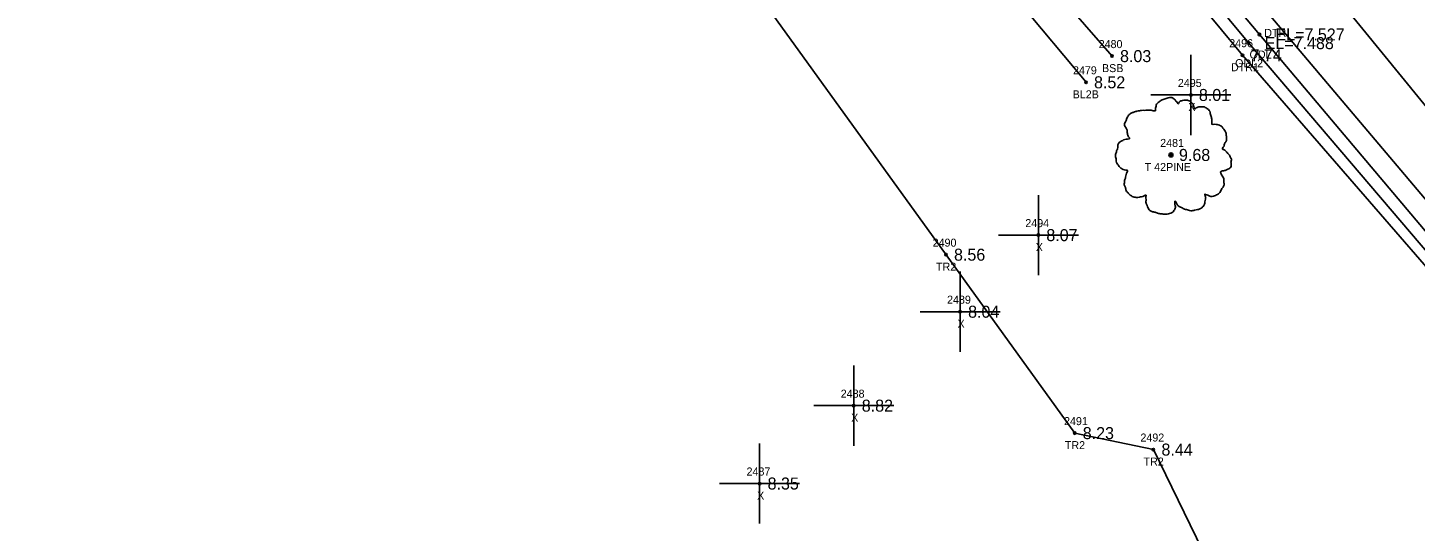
# Model space of a CAD drawing. Extents: x 2042211 to 2045853, y 303080 to 309569.
# Drawn here: x 2044468.4 to 2044641.9, y 304414.4 to 304477.2 of the extents above; entities that cross this region are included whole.
import ezdxf

# ---------------------------------------------------------------- set-up
doc = ezdxf.new("R2010")
doc.units = 0
for name, color, linetype in [('BR_500YR_SCOUR', 7, 'Continuous'), ('RD_DTM_BkLn1', 7, 'Continuous'), ('RD_DTM_BkLn2', 7, 'Continuous'), ('RD_DTM_BkLn_txCode', 7, 'Continuous'), ('RD_EX_H2O', 7, 'Continuous'), ('RD_EX_H2O_txCode', 7, 'Continuous'), ('RD_EX_Misc', 7, 'Continuous'), ('RD_EX_Misc_txCode', 7, 'Continuous'), ('RD_EX_TX_H2O_ELEV', 7, 'Continuous'), ('RD_EX_TX_Misc_ELEV', 7, 'Continuous'), ('RD_EX_TX_VEG_ELEV', 7, 'Continuous'), ('RD_EX_VEG_txCode', 7, 'Continuous'), ('RD_SMD_Locator', 7, 'Continuous')]:
    doc.layers.add(name, color=color, linetype=linetype)

msp = doc.modelspace()

# ---------------------------------------------------------------- linework, layer by layer
at = {"layer": 'BR_500YR_SCOUR'}
msp.add_lwpolyline([(2044509.17, 304539.98), (2044524.22, 304524.97), (2044542.12, 304505.8), (2044583.21, 304448.88), (2044599.3, 304426.6), (2044609.14, 304424.55), (2044616.83, 304408.81), (2044657.84, 304363.53)], dxfattribs=at)
for centre, radius in [((2044611.33, 304461.33), 0.25), ((2044611.33, 304461.33), 0.15), ((2044611.32, 304461.31), 0.0001), ((2044583.21, 304448.88), 0.15), ((2044599.3, 304426.6), 0.15), ((2044609.14, 304424.55), 0.15)]:
    msp.add_circle(centre, radius, dxfattribs=at)
for points in [[(2044611.46, 304468.5), (2044611.16, 304468.52), (2044610.84, 304468.42), (2044610.59, 304468.32), (2044610.36, 304468.25), (2044610.14, 304468.15), (2044609.84, 304467.97), (2044609.61, 304467.77), (2044609.49, 304467.53), (2044609.44, 304467.3), (2044609.39, 304467.03), (2044609.39, 304466.85), (2044609.26, 304466.83), (2044609.11, 304466.85), (2044608.86, 304466.93), (2044608.61, 304466.93), (2044608.36, 304466.93), (2044608.01, 304466.9), (2044607.66, 304466.9), (2044607.39, 304466.85), (2044607.06, 304466.8), (2044606.69, 304466.68), (2044606.34, 304466.55), (2044606.04, 304466.3), (2044605.79, 304465.83), (2044605.66, 304465.48), (2044605.51, 304465.23), (2044605.66, 304464.78), (2044605.84, 304464.43), (2044605.86, 304464.23), (2044605.94, 304463.8), (2044606.04, 304463.58), (2044606.16, 304463.38), (2044606.09, 304463.35), (2044605.71, 304463.3), (2044605.41, 304463.2), (2044604.99, 304462.98), (2044604.77, 304462.75), (2044604.67, 304462.43), (2044604.64, 304462.08), (2044604.54, 304461.88), (2044604.47, 304461.6), (2044604.44, 304461.53), (2044604.39, 304461.2), (2044604.49, 304460.75), (2044604.52, 304460.4), (2044604.64, 304460.18), (2044604.79, 304460), (2044604.96, 304459.75), (2044605.36, 304459.53), (2044605.69, 304459.43), (2044605.89, 304459.4), (2044605.71, 304458.9), (2044605.66, 304458.55), (2044605.54, 304458.15), (2044605.54, 304458.08), (2044605.49, 304457.6), (2044605.64, 304457.28), (2044605.71, 304456.9), (2044605.89, 304456.68), (2044606.16, 304456.38), (2044606.49, 304456.16), (2044606.99, 304456.03), (2044607.39, 304456.06), (2044607.96, 304456.23), (2044608.21, 304456.3), (2044608.19, 304456.13), (2044608.21, 304455.76), (2044608.21, 304455.33), (2044608.36, 304455.01), (2044608.46, 304454.73), (2044608.61, 304454.48), (2044608.94, 304454.26), (2044609.34, 304454.18), (2044609.76, 304454.03), (2044610.21, 304453.96), (2044610.71, 304453.93), (2044611.31, 304454.08), (2044611.59, 304454.21), (2044611.69, 304454.38), (2044611.89, 304454.76), (2044611.84, 304454.98), (2044611.86, 304455.58), (2044611.96, 304455.41), (2044612.14, 304455.06), (2044612.64, 304454.76), (2044613.04, 304454.58), (2044613.51, 304454.43), (2044613.81, 304454.36), (2044614.29, 304454.43), (2044614.66, 304454.51), (2044615.04, 304454.63), (2044615.34, 304454.91), (2044615.51, 304455.18), (2044615.56, 304455.46), (2044615.64, 304455.83), (2044615.69, 304456.01)], [(2044615.69, 304456.01), (2044615.61, 304456.18), (2044615.56, 304456.43), (2044615.64, 304456.4), (2044615.81, 304456.35), (2044616.09, 304456.23), (2044616.31, 304456.16), (2044616.63, 304456.18), (2044616.91, 304456.28), (2044617.36, 304456.55), (2044617.63, 304457.03), (2044617.91, 304457.43), (2044617.98, 304457.75), (2044617.93, 304457.98), (2044617.91, 304458.48), (2044617.71, 304458.73), (2044617.66, 304458.85), (2044617.56, 304459.25), (2044617.63, 304459.3), (2044617.91, 304459.35), (2044618.28, 304459.48), (2044618.56, 304459.6), (2044618.78, 304459.78), (2044618.86, 304460), (2044618.83, 304460.4), (2044618.88, 304460.8), (2044618.81, 304460.95), (2044618.71, 304461.1), (2044618.63, 304461.3), (2044618.48, 304461.45), (2044618.38, 304461.6), (2044618.28, 304461.7), (2044618.16, 304461.85), (2044617.98, 304461.98), (2044617.83, 304462.03), (2044617.78, 304462.18), (2044617.93, 304462.38), (2044617.98, 304462.48), (2044618.01, 304462.7), (2044618.23, 304463.05), (2044618.28, 304463.45), (2044618.23, 304463.88), (2044618.18, 304464.15), (2044618.03, 304464.43), (2044617.83, 304464.68), (2044617.71, 304464.85), (2044617.53, 304464.98), (2044617.21, 304465.1), (2044616.96, 304465.15), (2044616.61, 304465.15), (2044616.41, 304465.2), (2044616.43, 304465.25), (2044616.43, 304465.4), (2044616.43, 304465.68), (2044616.36, 304466.13), (2044616.21, 304466.63), (2044616.21, 304466.65), (2044616.11, 304466.9), (2044615.89, 304467.1), (2044615.71, 304467.2), (2044615.51, 304467.33), (2044615.26, 304467.35), (2044614.96, 304467.35), (2044614.69, 304467.3), (2044614.49, 304467.2), (2044614.31, 304467.08), (2044614.24, 304467.23), (2044614.14, 304467.53), (2044614.09, 304467.67), (2044613.94, 304467.85), (2044613.71, 304468.05), (2044613.26, 304468.17), (2044612.64, 304468.1), (2044612.34, 304467.9), (2044612.19, 304467.72), (2044612.14, 304467.85), (2044611.94, 304468.05), (2044611.84, 304468.22), (2044611.66, 304468.35), (2044611.51, 304468.45), (2044611.41, 304468.5)]]:
    msp.add_spline(points, degree=3, dxfattribs=at)
at = {"layer": 'RD_DTM_BkLn1'}
for points in [[(2043798.36, 305479.17), (2043862.32, 305402.71), (2043926.37, 305326.69), (2043989.74, 305249.79), (2043988.33, 305246.75), (2043991.19, 305243.51), (2043994.75, 305243.65), (2044053.09, 305173.37), (2044116.28, 305094.9), (2044180.2, 305019.52), (2044245.63, 304943.51), (2044308.37, 304866.05), (2044373.1, 304789.96), (2044438.35, 304712.62), (2044501.57, 304636.05), (2044528.47, 304600.32), (2044565.87, 304558.85), (2044630.47, 304482.97), (2044694.06, 304405.2), (2044697.06, 304397.81), (2044701.81, 304392.08), (2044707.96, 304388.87), (2044759.04, 304329.78)], [(2044527.03, 304557.93), (2044544.9, 304537.03), (2044600.71, 304470.4)]]:
    msp.add_lwpolyline(points, dxfattribs=at)
at = {"layer": 'RD_DTM_BkLn2'}
msp.add_lwpolyline([(2044528.83, 304561.67), (2044546.66, 304539.23), (2044603.96, 304473.67)], dxfattribs=at)
at = {"layer": 'RD_EX_H2O'}
for points in [[(2044526.69, 304588.12), (2044529.75, 304589.5), (2044560.23, 304553.15), (2044624.26, 304478.07), (2044679.39, 304412.98), (2044689.21, 304400.4), (2044696.61, 304396.14)], [(2044526.69, 304588.12), (2044524.46, 304585.8), (2044557.52, 304549.44), (2044620.27, 304473.78), (2044676.08, 304409.54), (2044675.89, 304404.78), (2044683.56, 304394.92), (2044688.93, 304389.15), (2044690.58, 304383.03), (2044681.72, 304360.31), (2044669.72, 304323.23)], [(2044528.02, 304587.51), (2044559.1, 304551.6), (2044622.39, 304476.37), (2044677.57, 304411.07), (2044687.25, 304399.14), (2044692.5, 304393.31)], [(2044526.69, 304586.11), (2044558.35, 304550.68), (2044621.04, 304475.29), (2044676.74, 304410.12), (2044678.19, 304404.53), (2044685.26, 304396.55), (2044691.41, 304390.93)]]:
    msp.add_lwpolyline(points, dxfattribs=at)
at = {"layer": 'RD_EX_Misc'}
for p, q in [((2044613.82, 304463.82), (2044613.82, 304473.82)), ((2044608.82, 304468.82), (2044618.82, 304468.82)), ((2044594.75, 304446.32), (2044594.75, 304456.32)), ((2044589.75, 304451.32), (2044599.75, 304451.32)), ((2044584.97, 304436.76), (2044584.97, 304446.76)), ((2044579.97, 304441.76), (2044589.97, 304441.76)), ((2044571.68, 304425.03), (2044571.68, 304435.03)), ((2044566.68, 304430.03), (2044576.68, 304430.03)), ((2044559.91, 304415.31), (2044559.91, 304425.31)), ((2044554.91, 304420.31), (2044564.91, 304420.31))]:
    msp.add_line(p, q, dxfattribs=at)
at = {"layer": 'RD_SMD_Locator'}
for centre in [(2044622.39, 304476.37), (2044621.04, 304475.29), (2044603.96, 304473.67), (2044620.27, 304473.78), (2044600.71, 304470.4), (2044613.82, 304468.82), (2044594.75, 304451.32), (2044584.97, 304441.76), (2044571.68, 304430.03), (2044559.91, 304420.31)]:
    msp.add_circle(centre, 0.15, dxfattribs=at)

# ---------------------------------------------------------------- texts
at = {"layer": 'RD_DTM_BkLn_txCode'}
for s, p in [('2480', (2044602.29, 304474.67)), ('BSB', (2044602.71, 304471.67)), ('2479', (2044599.08, 304471.4)), ('BL2B', (2044599.04, 304468.4))]:
    msp.add_text(s, height=1, dxfattribs=at).set_placement(p)
at = {"layer": 'RD_EX_H2O_txCode'}
for s, p in [('DTR', (2044622.99, 304476.07)), ('2496', (2044618.61, 304474.78)), ('ODL', (2044621.15, 304473.37)), ('DTR1', (2044618.83, 304471.78)), ('ODL2', (2044619.35, 304472.29))]:
    msp.add_text(s, height=1, dxfattribs=at).set_placement(p)
at = {"layer": 'RD_EX_Misc_txCode'}
for s, p in [('2495', (2044612.19, 304469.82)), ('X', (2044613.5, 304466.82)), ('2494', (2044593.12, 304452.32)), ('X', (2044594.43, 304449.32)), ('2489', (2044583.34, 304442.76)), ('X', (2044584.65, 304439.76)), ('2488', (2044570.05, 304431.03)), ('X', (2044571.36, 304428.03)), ('2487', (2044558.28, 304421.31)), ('X', (2044559.6, 304418.31))]:
    msp.add_text(s, height=1, dxfattribs=at).set_placement(p)
at = {"layer": 'RD_EX_TX_H2O_ELEV'}
for s, p in [('EL=7.488', (2044623.04, 304474.54)), ('EL=7.527', (2044624.39, 304475.62)), ('7.74', (2044621.27, 304473.03))]:
    msp.add_text(s, height=1.5, dxfattribs=at).set_placement(p)
at = {"layer": 'RD_EX_TX_Misc_ELEV'}
for s, p in [('8.03', (2044604.96, 304472.92)), ('8.52', (2044601.71, 304469.65)), ('8.01', (2044614.82, 304468.07)), ('8.07', (2044595.75, 304450.57)), ('8.04', (2044585.97, 304441.01)), ('8.82', (2044572.68, 304429.28)), ('8.35', (2044560.91, 304419.56))]:
    msp.add_text(s, height=1.5, dxfattribs=at).set_placement(p)
at = {"layer": 'RD_EX_TX_VEG_ELEV'}
for s, p in [('9.68', (2044612.33, 304460.58)), ('8.56', (2044584.21, 304448.13)), ('8.23', (2044600.3, 304425.85)), ('8.44', (2044610.14, 304423.8))]:
    msp.add_text(s, height=1.5, dxfattribs=at).set_placement(p)
at = {"layer": 'RD_EX_VEG_txCode'}
for s, p in [('2481', (2044609.98, 304462.33)), ('T 42PINE', (2044608.04, 304459.33)), ('2490', (2044581.54, 304449.88)), ('TR2', (2044581.96, 304446.88)), ('2491', (2044597.96, 304427.6)), ('2492', (2044607.51, 304425.55)), ('TR2', (2044598.06, 304424.6)), ('TR2', (2044607.9, 304422.55))]:
    msp.add_text(s, height=1, dxfattribs=at).set_placement(p)

doc.saveas('drawing.dxf')
